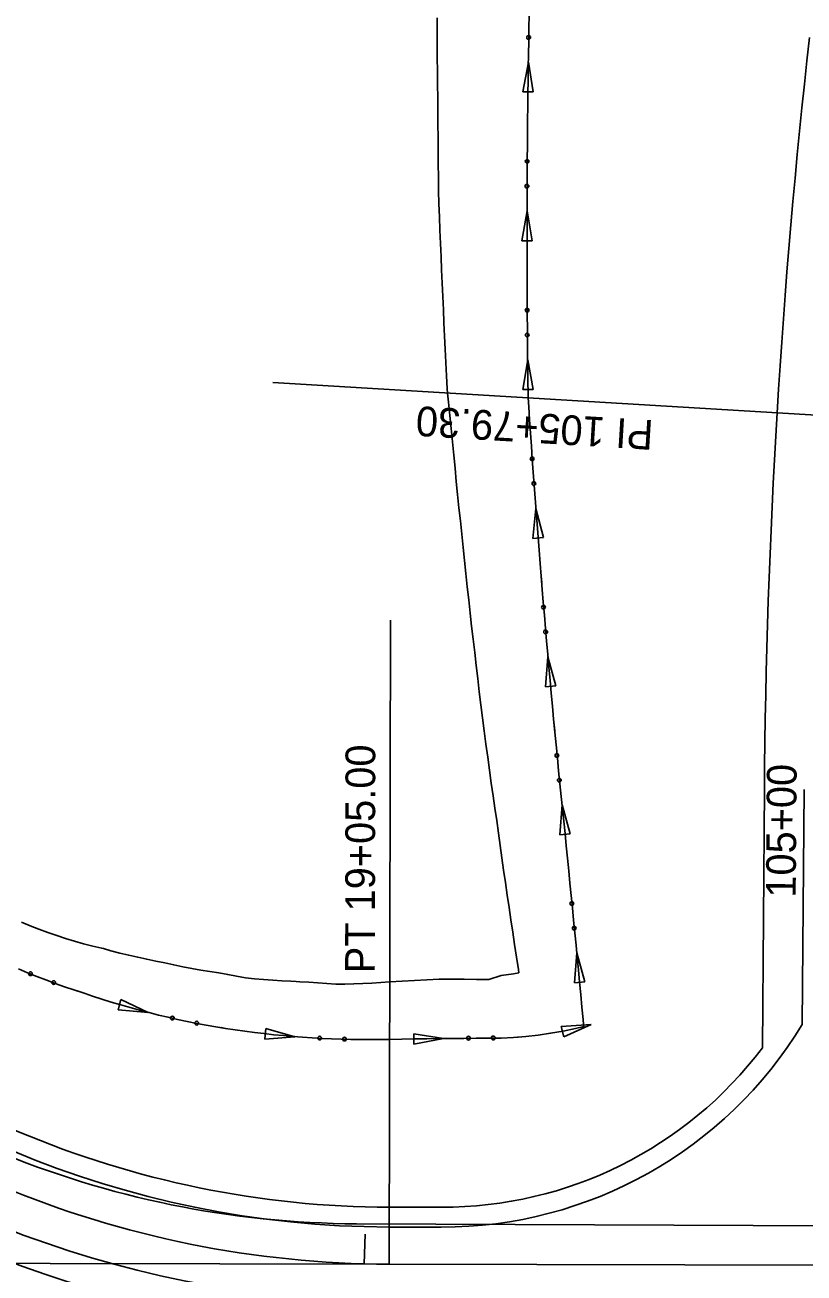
# Model space of a CAD drawing. Extents: x 1311167 to 1314552, y 2087587 to 2090602.
# Drawn here: x 1313823 to 1313980.2, y 2088407.4 to 2088659.3 of the extents above; entities that cross this region are included whole.
import ezdxf

# ---------------------------------------------------------------- set-up
doc = ezdxf.new("R2010")
doc.units = 0
for name, color, linetype in [('R_Bridge', 7, 'Continuous'), ('R_Guardrail', 7, 'Continuous'), ('R_Horz Alg Stationing', 7, 'Continuous'), ('R_Proposed Road', 7, 'Continuous'), ('R_Shld_GR', 7, 'Continuous'), ('R_Shoulder', 7, 'Continuous'), ('S_DITCHLINE', 7, 'Continuous'), ('S_EDGE_BITUMINOUS', 7, 'Continuous'), ('S_EDGE_CONCRETE', 7, 'Continuous'), ('S_EDGE_PAVEMENT', 7, 'Continuous'), ('S_PAVEMENT_CROWN', 7, 'Continuous')]:
    doc.layers.add(name, color=color, linetype=linetype)

msp = doc.modelspace()

# ---------------------------------------------------------------- linework, layer by layer
at = {"layer": 'R_Guardrail'}
msp.add_lwpolyline([(1313992.74, 2088579.98), (1313872.96, 2088587.18)], dxfattribs=at)
at = {"layer": 'R_Horz Alg Stationing'}
msp.add_line((1313889.89, 2088417.38), (1313991.5, 2088416.97), dxfattribs=at)
msp.add_arc((1313890.67, 2088608.34), 190.97, 179.7167, 269.7667, dxfattribs=at)
at = {"layer": 'R_Proposed Road'}
msp.add_line((1313896.44, 2088409.22), (1313991.44, 2088409.03), dxfattribs=at)
msp.add_line((1313896.44, 2088409.22), (1313991.44, 2088409.03), dxfattribs=at)
msp.add_arc((1313896.86, 2088613.85), 204.63, 179.7167, 269.8833, dxfattribs=at)
msp.add_arc((1313896.86, 2088613.85), 204.63, 179.7167, 269.8833, dxfattribs=at)
at = {"layer": 'R_Shld_GR'}
for points in [[(1313896.44, 2088409.22), (1313691.22, 2088409.64), (1313692.23, 2088614.86)], [(1313896.44, 2088409.22), (1313896.71, 2088539.22)]]:
    msp.add_lwpolyline(points, dxfattribs=at)
at = {"layer": 'R_Shoulder'}
msp.add_lwpolyline([(1313891.6, 2088415.29), (1313891.44, 2088409.29)], dxfattribs=at)
at = {"layer": 'S_DITCHLINE'}
for p, q in [((1313842.32, 2088462.62), (1313841.76, 2088460.58)), ((1313847.82, 2088460.01), (1313842.32, 2088462.62)), ((1313841.76, 2088460.58), (1313847.82, 2088460.01)), ((1313937.24, 2088457.61), (1313931.16, 2088457.17)), ((1313931.16, 2088457.17), (1313931.68, 2088455.12)), ((1313931.68, 2088455.12), (1313937.24, 2088457.61)), ((1313871.56, 2088456.76), (1313871.35, 2088454.65)), ((1313871.35, 2088454.65), (1313877.43, 2088455.12)), ((1313877.43, 2088455.12), (1313871.56, 2088456.76)), ((1313907.45, 2088454.75), (1313901.44, 2088455.74)), ((1313901.44, 2088455.74), (1313901.46, 2088453.62)), ((1313901.46, 2088453.62), (1313907.45, 2088454.75))]:
    msp.add_line(p, q, dxfattribs=at)
for points in [[(1313821.63, 2088468.82), (1313823.47, 2088468.05), (1313825.33, 2088467.31), (1313827.19, 2088466.59), (1313829.07, 2088465.9), (1313830.95, 2088465.23), (1313832.83, 2088464.6), (1313834.73, 2088463.98), (1313835.08, 2088463.87), (1313836.61, 2088463.35), (1313838.49, 2088462.72), (1313840.38, 2088462.13), (1313842.28, 2088461.56), (1313844.18, 2088461.01), (1313846.09, 2088460.49), (1313848, 2088459.99), (1313849.91, 2088459.51), (1313851.83, 2088459.05), (1313853.76, 2088458.62), (1313855.69, 2088458.21), (1313857.62, 2088457.83), (1313859.55, 2088457.47), (1313861.49, 2088457.13), (1313863.43, 2088456.81), (1313865.37, 2088456.52), (1313867.31, 2088456.24), (1313869.26, 2088455.99), (1313871.2, 2088455.75), (1313873.15, 2088455.54), (1313875.1, 2088455.35), (1313876.27, 2088455.24), (1313877.05, 2088455.18), (1313878.99, 2088455.03), (1313880.94, 2088454.9), (1313882.89, 2088454.79), (1313884.84, 2088454.7), (1313886.79, 2088454.63), (1313888.74, 2088454.58), (1313890.69, 2088454.56), (1313892.64, 2088454.55), (1313894.59, 2088454.56), (1313896.53, 2088454.6), (1313899.03, 2088454.64), (1313901.53, 2088454.68), (1313904.03, 2088454.71), (1313906.53, 2088454.74), (1313909.03, 2088454.77), (1313911.53, 2088454.79), (1313914.03, 2088454.81), (1313916.53, 2088454.83), (1313919.03, 2088454.87), (1313921.53, 2088454.98), (1313924.03, 2088455.18), (1313926.53, 2088455.46), (1313929.03, 2088455.82), (1313931.54, 2088456.27), (1313934.04, 2088456.8), (1313935.71, 2088457.22)], [(1313833.44, 2088464.4), (1313833.48, 2088464.39)], [(1313833.48, 2088464.39), (1313834.73, 2088463.98), (1313835.08, 2088463.87), (1313836.61, 2088463.35), (1313838.49, 2088462.72), (1313840.38, 2088462.13), (1313842.28, 2088461.56), (1313844.18, 2088461.01), (1313846.09, 2088460.49), (1313847.83, 2088460.03)], [(1313862.51, 2088456.96), (1313862.54, 2088456.96)], [(1313862.54, 2088456.96), (1313863.43, 2088456.81), (1313865.37, 2088456.52), (1313867.31, 2088456.24), (1313869.26, 2088455.99), (1313871.2, 2088455.75), (1313873.15, 2088455.54), (1313875.1, 2088455.35), (1313876.27, 2088455.24), (1313877.05, 2088455.18), (1313877.43, 2088455.15)], [(1313922.48, 2088455.06), (1313924.03, 2088455.18), (1313926.53, 2088455.46), (1313929.03, 2088455.82), (1313931.54, 2088456.27), (1313934.04, 2088456.8), (1313935.71, 2088457.22)], [(1313892.41, 2088454.55), (1313892.45, 2088454.55)], [(1313892.45, 2088454.55), (1313892.64, 2088454.55), (1313894.59, 2088454.56), (1313896.53, 2088454.6), (1313899.03, 2088454.64), (1313901.53, 2088454.68), (1313904.03, 2088454.71), (1313906.53, 2088454.74), (1313907.45, 2088454.75)], [(1313922.44, 2088455.06), (1313922.48, 2088455.06)]]:
    msp.add_lwpolyline(points, dxfattribs=at)
for centre in [(1313824.07, 2088467.85), (1313828.75, 2088466.06), (1313852.7, 2088458.9), (1313857.61, 2088457.87), (1313882.43, 2088454.85), (1313887.43, 2088454.65), (1313912.46, 2088454.84), (1313917.47, 2088454.88)]:
    msp.add_circle(centre, 0.375, dxfattribs=at)
at = {"layer": 'S_EDGE_BITUMINOUS'}
for p, q in [((1313924.55, 2088651.84), (1313923.4, 2088645.85)), ((1313924.55, 2088651.84), (1313923.4, 2088645.85)), ((1313925.52, 2088645.82), (1313924.55, 2088651.84)), ((1313925.52, 2088645.82), (1313924.55, 2088651.84)), ((1313923.4, 2088645.85), (1313925.52, 2088645.82)), ((1313923.4, 2088645.85), (1313925.52, 2088645.82)), ((1313924.28, 2088621.8), (1313923.22, 2088615.8)), ((1313924.28, 2088621.8), (1313923.22, 2088615.8)), ((1313925.33, 2088615.8), (1313924.28, 2088621.8)), ((1313925.33, 2088615.8), (1313924.28, 2088621.8)), ((1313923.22, 2088615.8), (1313925.33, 2088615.8)), ((1313923.22, 2088615.8), (1313925.33, 2088615.8)), ((1313924.41, 2088591.76), (1313923.42, 2088585.75)), ((1313924.41, 2088591.76), (1313923.42, 2088585.75)), ((1313925.54, 2088585.78), (1313924.41, 2088591.76)), ((1313925.54, 2088585.78), (1313924.41, 2088591.76)), ((1313923.42, 2088585.75), (1313925.54, 2088585.78)), ((1313923.42, 2088585.75), (1313925.54, 2088585.78)), ((1313926.06, 2088561.78), (1313925.46, 2088555.72)), ((1313926.06, 2088561.78), (1313925.46, 2088555.72)), ((1313927.57, 2088555.88), (1313926.06, 2088561.78)), ((1313927.57, 2088555.88), (1313926.06, 2088561.78)), ((1313925.46, 2088555.72), (1313927.57, 2088555.88)), ((1313925.46, 2088555.72), (1313927.57, 2088555.88)), ((1313928.49, 2088531.84), (1313927.98, 2088525.77)), ((1313928.49, 2088531.84), (1313927.98, 2088525.77)), ((1313930.08, 2088525.96), (1313928.49, 2088531.84)), ((1313930.08, 2088525.96), (1313928.49, 2088531.84)), ((1313927.98, 2088525.77), (1313930.08, 2088525.96)), ((1313927.98, 2088525.77), (1313930.08, 2088525.96)), ((1313931.34, 2088501.94), (1313930.9, 2088495.86)), ((1313931.34, 2088501.94), (1313930.9, 2088495.86)), ((1313933.01, 2088496.08), (1313931.34, 2088501.94)), ((1313933.01, 2088496.08), (1313931.34, 2088501.94)), ((1313930.9, 2088495.86), (1313933.01, 2088496.08)), ((1313930.9, 2088495.86), (1313933.01, 2088496.08)), ((1313934.32, 2088472.05), (1313933.84, 2088465.98)), ((1313934.32, 2088472.05), (1313933.84, 2088465.98)), ((1313935.94, 2088466.18), (1313934.32, 2088472.05)), ((1313935.94, 2088466.18), (1313934.32, 2088472.05)), ((1313933.84, 2088465.98), (1313935.94, 2088466.18)), ((1313933.84, 2088465.98), (1313935.94, 2088466.18))]:
    msp.add_line(p, q, dxfattribs=at)
for points in [[(1313935.72, 2088457.11), (1313935.71, 2088457.21), (1313935.7, 2088457.31), (1313935.68, 2088457.62), (1313935.58, 2088458.62), (1313935.35, 2088461.12), (1313935.12, 2088463.62), (1313934.88, 2088466.12), (1313934.65, 2088468.62), (1313934.41, 2088471.13), (1313934.17, 2088473.63), (1313933.93, 2088476.13), (1313933.68, 2088478.63), (1313933.44, 2088481.13), (1313933.19, 2088483.63), (1313932.94, 2088486.14), (1313932.69, 2088488.64), (1313932.44, 2088491.14), (1313932.19, 2088493.64), (1313931.94, 2088496.14), (1313931.68, 2088498.65), (1313931.42, 2088501.15), (1313931.16, 2088503.65), (1313930.9, 2088506.19), (1313930.64, 2088508.8), (1313930.39, 2088511.41), (1313930.14, 2088514.02), (1313929.89, 2088516.63), (1313929.64, 2088519.24), (1313929.4, 2088521.86), (1313929.16, 2088524.47), (1313928.92, 2088527.09), (1313928.68, 2088529.71), (1313928.45, 2088532.33), (1313928.22, 2088534.94), (1313928, 2088537.56), (1313927.78, 2088540.19), (1313927.56, 2088542.81), (1313927.34, 2088545.43), (1313927.13, 2088548.06), (1313926.92, 2088550.68), (1313926.71, 2088553.31), (1313926.5, 2088555.93), (1313926.3, 2088558.56), (1313926.1, 2088561.19), (1313925.91, 2088563.82), (1313925.71, 2088566.45), (1313925.52, 2088569.08), (1313925.34, 2088571.71), (1313925.15, 2088574.35), (1313924.97, 2088576.98), (1313924.8, 2088579.62), (1313924.62, 2088582.26), (1313924.5, 2088584.08), (1313924.49, 2088584.89), (1313924.46, 2088587.52), (1313924.42, 2088590.15), (1313924.4, 2088592.78), (1313924.37, 2088595.41), (1313924.35, 2088598.05), (1313924.33, 2088600.68), (1313924.31, 2088603.31), (1313924.3, 2088605.95), (1313924.29, 2088608.58), (1313924.28, 2088611.21), (1313924.28, 2088613.85), (1313924.28, 2088616.48), (1313924.28, 2088619.12), (1313924.28, 2088621.76), (1313924.29, 2088624.39), (1313924.3, 2088627.03), (1313924.31, 2088629.67), (1313924.33, 2088632.31), (1313924.35, 2088634.95), (1313924.37, 2088637.59), (1313924.4, 2088640.23), (1313924.43, 2088642.87), (1313924.46, 2088645.51), (1313924.49, 2088648.15), (1313924.53, 2088650.79), (1313924.57, 2088653.44), (1313924.62, 2088656.08), (1313924.67, 2088658.72), (1313924.72, 2088661.37)], [(1313924.37, 2088636.84), (1313924.37, 2088637.59), (1313924.4, 2088640.23), (1313924.43, 2088642.87), (1313924.46, 2088645.51), (1313924.49, 2088648.15), (1313924.53, 2088650.79), (1313924.55, 2088651.84)], [(1313924.37, 2088636.84), (1313924.37, 2088637.59), (1313924.4, 2088640.23), (1313924.43, 2088642.87), (1313924.46, 2088645.51), (1313924.49, 2088648.15), (1313924.53, 2088650.79), (1313924.55, 2088651.84)], [(1313924.37, 2088636.8), (1313924.37, 2088636.84)], [(1313924.37, 2088636.8), (1313924.37, 2088636.84)], [(1313924.3, 2088606.8), (1313924.29, 2088608.58), (1313924.28, 2088611.21), (1313924.28, 2088613.85), (1313924.28, 2088616.48), (1313924.28, 2088619.12), (1313924.28, 2088621.76), (1313924.28, 2088621.8)], [(1313924.3, 2088606.8), (1313924.29, 2088608.58), (1313924.28, 2088611.21), (1313924.28, 2088613.85), (1313924.28, 2088616.48), (1313924.28, 2088619.12), (1313924.28, 2088621.76), (1313924.28, 2088621.8)], [(1313924.3, 2088606.76), (1313924.3, 2088606.8)], [(1313924.3, 2088606.76), (1313924.3, 2088606.8)], [(1313924.99, 2088576.78), (1313924.97, 2088576.98), (1313924.8, 2088579.62), (1313924.62, 2088582.26), (1313924.5, 2088584.08), (1313924.49, 2088584.89), (1313924.46, 2088587.52), (1313924.42, 2088590.15), (1313924.41, 2088591.76)], [(1313924.99, 2088576.78), (1313924.97, 2088576.98), (1313924.8, 2088579.62), (1313924.62, 2088582.26), (1313924.5, 2088584.08), (1313924.49, 2088584.89), (1313924.46, 2088587.52), (1313924.42, 2088590.15), (1313924.41, 2088591.76)], [(1313924.99, 2088576.74), (1313924.99, 2088576.78)], [(1313924.99, 2088576.74), (1313924.99, 2088576.78)], [(1313927.23, 2088546.83), (1313927.13, 2088548.06), (1313926.92, 2088550.68), (1313926.71, 2088553.31), (1313926.5, 2088555.93), (1313926.3, 2088558.56), (1313926.1, 2088561.19), (1313926.06, 2088561.78)], [(1313927.23, 2088546.83), (1313927.13, 2088548.06), (1313926.92, 2088550.68), (1313926.71, 2088553.31), (1313926.5, 2088555.93), (1313926.3, 2088558.56), (1313926.1, 2088561.19), (1313926.06, 2088561.78)], [(1313927.23, 2088546.79), (1313927.23, 2088546.83)], [(1313927.23, 2088546.79), (1313927.23, 2088546.83)], [(1313929.86, 2088516.9), (1313929.64, 2088519.24), (1313929.4, 2088521.86), (1313929.16, 2088524.47), (1313928.92, 2088527.09), (1313928.68, 2088529.71), (1313928.5, 2088531.84)], [(1313929.86, 2088516.9), (1313929.64, 2088519.24), (1313929.4, 2088521.86), (1313929.16, 2088524.47), (1313928.92, 2088527.09), (1313928.68, 2088529.71), (1313928.5, 2088531.84)], [(1313929.86, 2088516.87), (1313929.86, 2088516.9)], [(1313929.86, 2088516.87), (1313929.86, 2088516.9)], [(1313932.86, 2088487.02), (1313932.69, 2088488.64), (1313932.44, 2088491.14), (1313932.19, 2088493.64), (1313931.94, 2088496.14), (1313931.68, 2088498.65), (1313931.42, 2088501.15), (1313931.34, 2088501.94)], [(1313932.86, 2088487.02), (1313932.69, 2088488.64), (1313932.44, 2088491.14), (1313932.19, 2088493.64), (1313931.94, 2088496.14), (1313931.68, 2088498.65), (1313931.42, 2088501.15), (1313931.34, 2088501.94)], [(1313932.86, 2088486.98), (1313932.86, 2088487.02)], [(1313932.86, 2088486.98), (1313932.86, 2088487.02)], [(1313935.72, 2088457.11), (1313935.71, 2088457.21), (1313935.7, 2088457.31), (1313935.68, 2088457.62), (1313935.58, 2088458.62), (1313935.35, 2088461.12), (1313935.12, 2088463.62), (1313934.88, 2088466.12), (1313934.65, 2088468.62), (1313934.41, 2088471.13), (1313934.32, 2088472.05)], [(1313935.72, 2088457.11), (1313935.71, 2088457.21), (1313935.7, 2088457.31), (1313935.68, 2088457.62), (1313935.58, 2088458.62), (1313935.35, 2088461.12), (1313935.12, 2088463.62), (1313934.88, 2088466.12), (1313934.65, 2088468.62), (1313934.41, 2088471.13), (1313934.32, 2088472.05)]]:
    msp.add_lwpolyline(points, dxfattribs=at)
for centre in [(1313924.6, 2088656.84), (1313924.6, 2088656.84), (1313924.29, 2088631.82), (1313924.29, 2088631.82), (1313924.26, 2088626.81), (1313924.26, 2088626.81), (1313924.29, 2088601.78), (1313924.29, 2088601.78), (1313924.32, 2088596.77), (1313924.32, 2088596.77), (1313925.3, 2088571.77), (1313925.3, 2088571.77), (1313925.66, 2088566.77), (1313925.66, 2088566.77), (1313927.6, 2088541.82), (1313927.6, 2088541.82), (1313928.03, 2088536.83), (1313928.03, 2088536.83), (1313930.3, 2088511.9), (1313930.3, 2088511.9), (1313930.79, 2088506.91), (1313930.79, 2088506.91), (1313933.32, 2088482.01), (1313933.32, 2088482.01), (1313933.8, 2088477.03), (1313933.8, 2088477.03)]:
    msp.add_circle(centre, 0.375, dxfattribs=at)
at = {"layer": 'S_EDGE_CONCRETE'}
for points in [[(1313922.62, 2088468.03), (1313922.52, 2088468.72), (1313922.14, 2088471.22), (1313921.77, 2088473.72), (1313921.4, 2088476.22), (1313921.02, 2088478.73), (1313920.65, 2088481.23), (1313920.27, 2088483.73), (1313919.91, 2088486.24), (1313919.56, 2088488.74), (1313919.21, 2088491.24), (1313918.86, 2088493.74), (1313918.51, 2088496.25), (1313918.15, 2088498.75), (1313917.78, 2088501.25), (1313917.42, 2088503.76), (1313917.06, 2088506.3), (1313916.7, 2088508.93), (1313916.34, 2088511.57), (1313915.99, 2088514.21), (1313915.64, 2088516.85), (1313915.28, 2088519.49), (1313914.93, 2088522.13), (1313914.63, 2088524.77), (1313914.33, 2088527.41), (1313914.04, 2088530.06), (1313913.73, 2088532.7), (1313913.39, 2088535.35), (1313913.06, 2088538), (1313912.77, 2088540.65), (1313912.5, 2088543.3), (1313912.22, 2088545.95), (1313911.95, 2088548.6), (1313911.68, 2088551.26), (1313911.42, 2088553.91), (1313911.14, 2088556.57), (1313910.84, 2088559.23), (1313910.54, 2088561.89), (1313910.26, 2088564.55), (1313910, 2088567.21), (1313909.76, 2088569.87), (1313909.5, 2088572.54), (1313909.24, 2088575.2), (1313908.97, 2088577.87), (1313908.71, 2088580.54), (1313908.42, 2088583.21), (1313908.22, 2088585.06), (1313908.17, 2088585.88), (1313908.02, 2088588.55), (1313907.88, 2088591.21), (1313907.73, 2088593.88), (1313907.6, 2088596.55), (1313907.5, 2088599.21), (1313907.4, 2088601.88), (1313907.3, 2088604.55), (1313907.17, 2088607.22), (1313907.04, 2088609.9), (1313906.92, 2088612.57), (1313906.8, 2088615.25), (1313906.69, 2088617.92), (1313906.58, 2088620.6), (1313906.51, 2088623.27), (1313906.44, 2088625.95), (1313906.38, 2088628.62), (1313906.36, 2088631.29), (1313906.34, 2088633.97), (1313906.32, 2088636.64), (1313906.3, 2088639.32), (1313906.29, 2088641.99), (1313906.28, 2088644.67), (1313906.24, 2088647.35), (1313906.2, 2088650.03), (1313906.16, 2088652.71), (1313906.15, 2088655.4), (1313906.15, 2088658.08), (1313906.16, 2088660.76)], [(1313822.24, 2088478.22), (1313824.01, 2088477.51), (1313825.78, 2088476.84), (1313827.57, 2088476.19), (1313829.36, 2088475.57), (1313831.17, 2088474.99), (1313832.97, 2088474.43), (1313834.79, 2088473.9), (1313836.63, 2088473.44), (1313838.46, 2088472.99), (1313838.8, 2088472.91), (1313840.27, 2088472.5), (1313842.08, 2088472.02), (1313843.9, 2088471.58), (1313845.72, 2088471.16), (1313847.54, 2088470.76), (1313849.37, 2088470.4), (1313851.19, 2088470.04), (1313853, 2088469.64), (1313854.8, 2088469.26), (1313856.62, 2088468.91), (1313858.43, 2088468.59), (1313860.25, 2088468.29), (1313862.07, 2088468.01), (1313863.87, 2088467.66), (1313865.67, 2088467.33), (1313867.47, 2088467.02), (1313869.3, 2088466.82), (1313871.12, 2088466.66), (1313872.95, 2088466.52), (1313874.78, 2088466.41), (1313876.6, 2088466.32), (1313877.7, 2088466.27), (1313878.43, 2088466.24), (1313880.24, 2088466.13), (1313882.05, 2088465.99), (1313883.87, 2088465.87), (1313885.68, 2088465.77), (1313887.5, 2088465.76), (1313889.31, 2088465.81), (1313891.13, 2088465.87), (1313892.94, 2088465.96), (1313894.75, 2088466.07), (1313896.56, 2088466.19), (1313899.06, 2088466.35), (1313901.56, 2088466.49), (1313904.06, 2088466.64), (1313906.56, 2088466.78), (1313909.06, 2088466.78), (1313911.56, 2088466.75), (1313914.06, 2088466.71), (1313916.56, 2088466.68), (1313919.06, 2088467.5), (1313921.56, 2088467.85), (1313922.62, 2088468.03)]]:
    msp.add_lwpolyline(points, dxfattribs=at)
at = {"layer": 'S_EDGE_PAVEMENT'}
for p, q in [((1313971.77, 2088452.87), (1313972.17, 2088505.07)), ((1313896.46, 2088420.72), (1313906.98, 2088420.7))]:
    msp.add_line(p, q, dxfattribs=at)
for centre, radius, start, end in [((1315424.52, 2088493.98), 1452.39, 173.5625, 179.5625), ((1313896.86, 2088613.85), 193.13, 178.6953, 269.8833), ((1313896.86, 2088613.85), 218.13, 184.1502, 262.6016), ((1313907.14, 2088501.7), 81, 269.8833, 322.929)]:
    msp.add_arc(centre, radius, start, end, dxfattribs=at)
at = {"layer": 'S_PAVEMENT_CROWN'}
for p, q in [((1313979.81, 2088457.6), (1313980.17, 2088505.01)), ((1313896.46, 2088416.72), (1313906.97, 2088416.7))]:
    msp.add_line(p, q, dxfattribs=at)
for centre, radius, start, end in [((1313896.86, 2088613.85), 197.13, 180.9321, 269.8833), ((1313896.86, 2088613.85), 212.13, 181.1378, 262.6016), ((1313907.14, 2088501.7), 85, 269.8833, 328.7472)]:
    msp.add_arc(centre, radius, start, end, dxfattribs=at)

# ---------------------------------------------------------------- texts
at = {"layer": 'R_Bridge'}
msp.add_text('105+00', height=6, rotation=89.5625, dxfattribs=at).set_placement((1313978.49, 2088483.18))
at = {"layer": 'R_Guardrail'}
msp.add_text('PI 105+79.30', height=6, rotation=176.5625, dxfattribs=at).set_placement((1313949.93, 2088579.55))
at = {"layer": 'R_Shld_GR'}
msp.add_text('PT 19+05.00', height=6, rotation=89.8833, dxfattribs=at).set_placement((1313893.56, 2088467.94))

doc.saveas('drawing.dxf')
